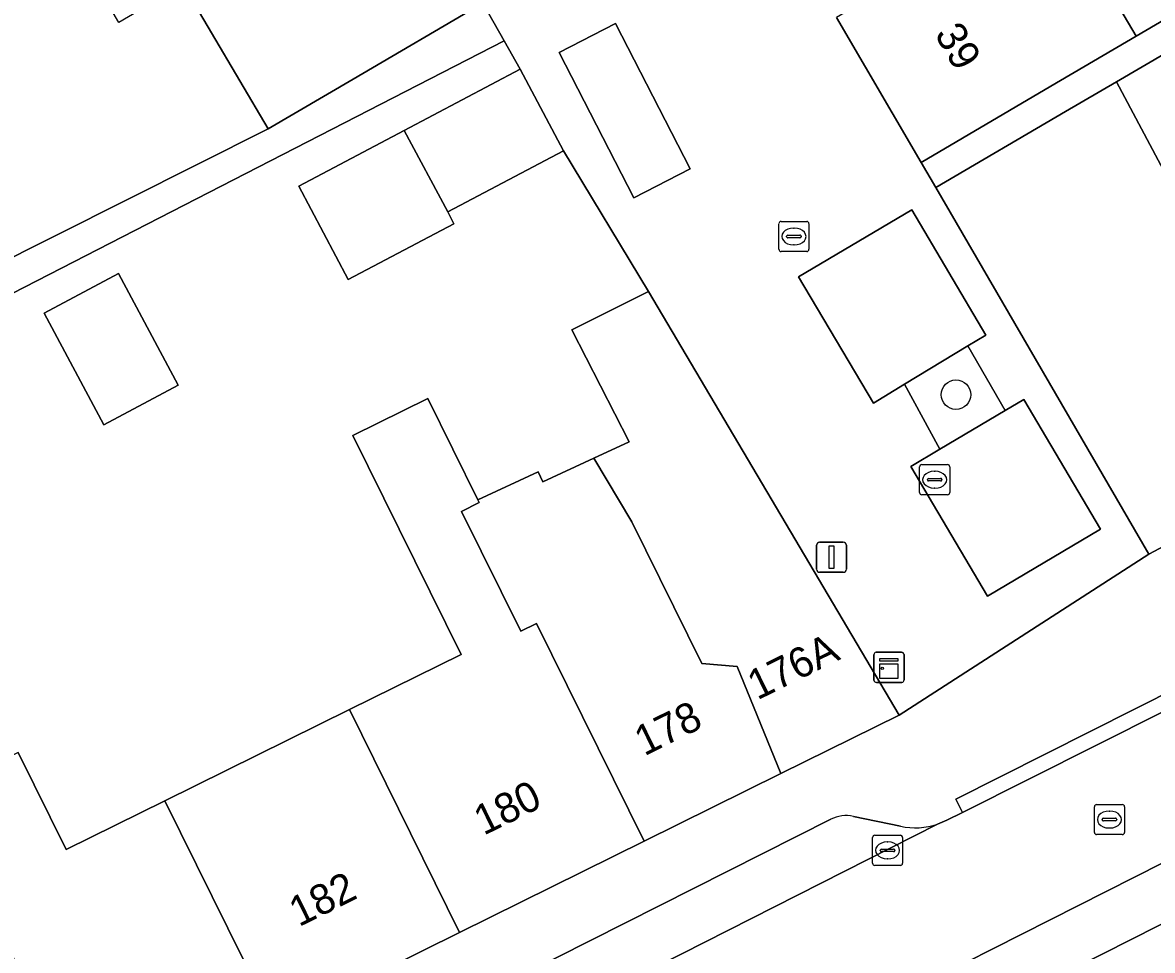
# Model space of a CAD drawing. Extents: x 161771 to 163125, y 382475 to 383179.
# Drawn here: x 162276.97 to 162314.5, y 382695.7 to 382726.52 of the extents above; entities that cross this region are included whole.
import ezdxf

# ---------------------------------------------------------------- set-up
doc = ezdxf.new("R2010")
doc.units = 0
for name, color, linetype in [('IMGEO_Boom', 7, 'Continuous'), ('IMGEO_Erf', 7, 'Continuous'), ('IMGEO_Groenvoorziening', 7, 'Continuous'), ('IMGEO_Kast', 7, 'Continuous'), ('IMGEO_Kolk', 7, 'Continuous'), ('IMGEO_Lichtmast', 7, 'Continuous'), ('IMGEO_Muur', 7, 'Continuous'), ('IMGEO_Pand', 7, 'Continuous'), ('IMGEO_Pand_nummerreeks', 7, 'Continuous'), ('IMGEO_Parkeervlak_open', 7, 'Continuous'), ('IMGEO_Rijbaan_lokaal_open', 7, 'Continuous'), ('IMGEO_Rioolput', 7, 'Continuous'), ('IMGEO_Voetpad_open', 7, 'Continuous'), ('IMGEO_Woonerf_open', 7, 'Continuous')]:
    doc.layers.add(name, color=color, linetype=linetype)

msp = doc.modelspace()

# ---------------------------------------------------------------- linework, layer by layer
at = {"layer": 'IMGEO_Boom'}
msp.add_circle((162307.974, 382714.16), 0.489, dxfattribs=at)
at = {"layer": 'IMGEO_Erf'}
for points in [[(162275.724, 382718.276), (162285.12, 382722.995), (162282.305, 382727.783), (162280.165, 382726.529), (162277.514, 382731.054), (162274.864, 382735.578), (162276.989, 382736.823), (162274.331, 382741.344)], [(162320.333, 382736.234), (162311.14, 382730.859), (162313.959, 382726.072), (162319.628, 382729.406)], [(162276.82, 382702.277), (162278.412, 382699.054), (162281.691, 382700.673), (162287.824, 382703.703), (162291.531, 382705.534), (162287.94, 382712.804), (162290.429, 382714.032), (162292.093, 382710.663), (162294.095, 382711.595), (162294.25, 382711.263), (162295.939, 382712.049), (162297.114, 382712.596), (162295.216, 382716.318), (162297.757, 382717.589), (162294.932, 382722.26), (162291.09, 382720.229), (162291.297, 382719.84), (162287.785, 382717.983), (162286.143, 382721.089), (162289.645, 382722.94), (162293.496, 382724.976), (162292.966, 382725.916), (162274.561, 382716.472)]]:
    msp.add_lwpolyline(points, dxfattribs=at)
msp.add_lwpolyline([(162277.677, 382716.867), (162280.154, 382718.19), (162282.137, 382714.479), (162279.661, 382713.156)], close=True, dxfattribs=at)
at = {"layer": 'IMGEO_Groenvoorziening'}
msp.add_lwpolyline([(162307.44, 382712.352), (162309.608, 382713.635), (162308.371, 382715.782), (162306.267, 382714.505)], close=True, dxfattribs=at)
at = {"layer": 'IMGEO_Kast'}
for p, q in [((162305.248, 382704.676), (162305.248, 382705.517)), ((162305.248, 382705.517), (162305.248, 382704.676)), ((162305.323, 382705.601), (162306.164, 382705.601)), ((162306.164, 382705.601), (162305.323, 382705.601)), ((162306.248, 382705.526), (162306.248, 382704.685)), ((162306.248, 382704.685), (162306.248, 382705.526)), ((162306.173, 382704.601), (162305.332, 382704.601)), ((162305.332, 382704.601), (162306.173, 382704.601))]:
    msp.add_line(p, q, dxfattribs=at)
for points in [[(162305.443, 382705.391), (162306.043, 382705.391), (162306.043, 382705.306), (162305.443, 382705.306), (162305.443, 382705.391)], [(162305.443, 382705.216), (162306.043, 382705.216), (162306.043, 382704.727), (162305.443, 382704.727), (162305.443, 382705.216)]]:
    msp.add_lwpolyline(points, dxfattribs=at)
msp.add_circle((162305.527, 382705.065), 0.0377, dxfattribs=at)
for centre, start, end in [((162305.326, 382705.523), 92.4484, 184.2845), ((162305.326, 382705.523), 92.4484, 184.2845), ((162306.17, 382705.523), 2.4484, 94.2845), ((162306.17, 382705.523), 2.4484, 94.2845), ((162305.326, 382704.679), 182.4484, 274.2845), ((162305.326, 382704.679), 182.4484, 274.2845), ((162306.17, 382704.679), 272.4484, 4.2845), ((162306.17, 382704.679), 272.4484, 4.2845)]:
    msp.add_arc(centre, 0.0779, start, end, dxfattribs=at)
at = {"layer": 'IMGEO_Kolk'}
for p, q in [((162302.09, 382718.989), (162302.09, 382719.841)), ((162302.165, 382719.915), (162303.017, 382719.915)), ((162302.578, 382719.695), (162302.603, 382719.695)), ((162303.091, 382719.841), (162303.091, 382718.989)), ((162302.349, 382719.409), (162302.349, 382719.421)), ((162302.787, 382719.372), (162302.389, 382719.372)), ((162302.392, 382719.458), (162302.79, 382719.458)), ((162302.833, 382719.421), (162302.833, 382719.409)), ((162303.017, 382718.915), (162302.165, 382718.915)), ((162302.601, 382719.135), (162302.576, 382719.135)), ((162306.766, 382710.91), (162306.766, 382711.762)), ((162306.841, 382711.836), (162307.693, 382711.836)), ((162307.767, 382711.762), (162307.767, 382710.91)), ((162307.025, 382711.33), (162307.025, 382711.342)), ((162307.068, 382711.379), (162307.466, 382711.379)), ((162307.254, 382711.616), (162307.279, 382711.616)), ((162307.509, 382711.342), (162307.509, 382711.33)), ((162307.463, 382711.293), (162307.065, 382711.293)), ((162307.277, 382711.056), (162307.252, 382711.056)), ((162307.693, 382710.836), (162306.841, 382710.836)), ((162305.201, 382698.596), (162305.201, 382699.448)), ((162305.276, 382699.522), (162306.128, 382699.522)), ((162306.202, 382699.448), (162306.202, 382698.596)), ((162305.46, 382699.016), (162305.46, 382699.028)), ((162305.898, 382698.979), (162305.5, 382698.979)), ((162305.503, 382699.065), (162305.901, 382699.065)), ((162305.689, 382699.302), (162305.714, 382699.302)), ((162305.944, 382699.028), (162305.944, 382699.016)), ((162305.712, 382698.742), (162305.687, 382698.742)), ((162306.128, 382698.522), (162305.276, 382698.522))]:
    msp.add_line(p, q, dxfattribs=at)
for points in [[(162302.09, 382718.989), (162302.09, 382719.841)], [(162302.165, 382719.915), (162303.017, 382719.915)], [(162303.091, 382719.841), (162303.091, 382718.989)], [(162303.017, 382718.915), (162302.165, 382718.915)], [(162306.766, 382710.91), (162306.766, 382711.762)], [(162306.841, 382711.836), (162307.693, 382711.836)], [(162307.767, 382711.762), (162307.767, 382710.91)], [(162307.693, 382710.836), (162306.841, 382710.836)], [(162305.201, 382698.596), (162305.201, 382699.448)], [(162305.276, 382699.522), (162306.128, 382699.522)], [(162306.202, 382699.448), (162306.202, 382698.596)], [(162306.128, 382698.522), (162305.276, 382698.522)]]:
    msp.add_lwpolyline(points, dxfattribs=at)
for centre, radius, start, end in [((162302.167, 382719.839), 0.0765, 91.552, 178.448), ((162302.167, 382719.839), 0.0765, 91.552, 178.448), ((162303.015, 382719.839), 0.0765, 1.552, 88.448), ((162303.015, 382719.839), 0.0765, 1.552, 88.448), ((162302.389, 382719.418), 0.0403, 85.8775, 175.7526), ((162302.386, 382719.408), 0.0366, 178.938, 274.7102), ((162302.79, 382719.415), 0.043, 264.8664, 352.4533), ((162302.794, 382719.42), 0.0386, 1.7309, 96.639), ((162302.167, 382718.991), 0.0765, 181.552, 268.448), ((162302.167, 382718.991), 0.0765, 181.552, 268.448), ((162303.015, 382718.991), 0.0765, 271.552, 358.448), ((162303.015, 382718.991), 0.0765, 271.552, 358.448), ((162306.843, 382711.76), 0.0765, 91.552, 178.448), ((162306.843, 382711.76), 0.0765, 91.552, 178.448), ((162307.691, 382711.76), 0.0765, 1.552, 88.448), ((162307.691, 382711.76), 0.0765, 1.552, 88.448), ((162307.065, 382711.339), 0.0403, 85.8775, 175.7526), ((162307.47, 382711.341), 0.0386, 1.7309, 96.639), ((162307.062, 382711.329), 0.0366, 178.938, 274.7102), ((162307.466, 382711.336), 0.043, 264.8664, 352.4533), ((162306.843, 382710.912), 0.0765, 181.552, 268.448), ((162306.843, 382710.912), 0.0765, 181.552, 268.448), ((162307.691, 382710.912), 0.0765, 271.552, 358.448), ((162307.691, 382710.912), 0.0765, 271.552, 358.448), ((162305.278, 382699.446), 0.0765, 91.552, 178.448), ((162305.278, 382699.446), 0.0765, 91.552, 178.448), ((162306.126, 382699.446), 0.0765, 1.552, 88.448), ((162306.126, 382699.446), 0.0765, 1.552, 88.448), ((162305.5, 382699.025), 0.0403, 85.8775, 175.7526), ((162305.497, 382699.015), 0.0366, 178.938, 274.7102), ((162305.901, 382699.022), 0.043, 264.8664, 352.4533), ((162305.905, 382699.027), 0.0386, 1.7309, 96.639), ((162305.278, 382698.598), 0.0765, 181.552, 268.448), ((162305.278, 382698.598), 0.0765, 181.552, 268.448), ((162306.126, 382698.598), 0.0765, 271.552, 358.448), ((162306.126, 382698.598), 0.0765, 271.552, 358.448)]:
    msp.add_arc(centre, radius, start, end, dxfattribs=at)
for centre, major_axis, ratio, start_param, end_param in [((162302.577, 382719.415), (-0.387, 0.002), 0.722429, 4.712389, 7.853982), ((162302.602, 382719.415), (-0.39, 0.002), 0.717154, 1.570796, 4.712389), ((162307.253, 382711.336), (-0.387, 0.002), 0.722429, 4.712389, 7.853982), ((162307.278, 382711.336), (-0.39, 0.002), 0.717154, 1.570796, 4.712389), ((162305.688, 382699.022), (-0.387, 0.002), 0.722429, 4.712389, 7.853982), ((162305.713, 382699.022), (-0.39, 0.002), 0.717154, 1.570796, 4.712389)]:
    msp.add_ellipse(centre, major_axis=major_axis, ratio=ratio, start_param=start_param, end_param=end_param, dxfattribs=at)
at = {"layer": 'IMGEO_Lichtmast'}
for p, q in [((162303.342, 382708.36), (162303.342, 382709.16)), ((162303.342, 382709.16), (162303.342, 382708.36)), ((162303.442, 382709.26), (162304.232, 382709.26)), ((162304.232, 382709.26), (162303.442, 382709.26)), ((162304.332, 382709.16), (162304.332, 382708.36)), ((162304.332, 382708.36), (162304.332, 382709.16)), ((162304.232, 382708.26), (162303.442, 382708.26)), ((162303.442, 382708.26), (162304.232, 382708.26))]:
    msp.add_line(p, q, dxfattribs=at)
msp.add_lwpolyline([(162303.762, 382709.135), (162303.912, 382709.135), (162303.912, 382708.385), (162303.762, 382708.385), (162303.762, 382709.135)], dxfattribs=at)
for centre, start, end in [((162303.442, 382709.16), 90, 180), ((162303.442, 382709.16), 90, 180), ((162304.232, 382709.16), 0, 90), ((162304.232, 382709.16), 360, 90), ((162303.442, 382708.36), 180, 270), ((162303.442, 382708.36), 180, 270), ((162304.232, 382708.36), 270, 0), ((162304.232, 382708.36), 270, 0)]:
    msp.add_arc(centre, 0.1, start, end, dxfattribs=at)
at = {"layer": 'IMGEO_Muur'}
msp.add_lwpolyline([(162297.757, 382717.589), (162294.932, 382722.26)], dxfattribs=at)
at = {"layer": 'IMGEO_Pand'}
for points in [[(162282.305, 382727.783), (162285.12, 382722.995), (162287.943, 382724.646), (162292.259, 382727.17), (162289.442, 382731.963)], [(162311.14, 382730.859), (162310.946, 382730.745), (162304.003, 382726.686), (162306.82, 382721.874), (162311.131, 382724.409), (162313.959, 382726.072)], [(162321.429, 382722.643), (162318.523, 382721.051), (162318.3, 382721.471), (162315.862, 382726.049), (162313.303, 382724.551), (162320.055, 382711.869), (162325.601, 382714.806)], [(162289.645, 382722.94), (162291.09, 382720.229), (162294.932, 382722.26), (162293.496, 382724.976)], [(162313.303, 382724.551), (162311.616, 382723.563), (162307.301, 382721.037), (162314.379, 382708.865), (162320.055, 382711.869)], [(162289.645, 382722.94), (162286.143, 382721.089), (162287.785, 382717.983), (162291.297, 382719.84), (162291.09, 382720.229)], [(162277.677, 382716.867), (162279.661, 382713.156), (162282.137, 382714.479), (162280.154, 382718.19)], [(162295.939, 382712.049), (162297.206, 382709.941), (162299.535, 382705.226), (162300.705, 382705.133), (162302.155, 382701.574), (162306.086, 382703.518), (162297.757, 382717.589), (162295.216, 382716.318), (162297.114, 382712.596)], [(162297.616, 382699.329), (162294.043, 382706.564), (162293.514, 382706.303), (162291.549, 382710.283), (162292.137, 382710.573), (162292.093, 382710.663), (162290.429, 382714.032), (162287.94, 382712.804), (162291.531, 382705.534), (162287.824, 382703.703), (162291.483, 382696.295)], [(162297.616, 382699.329), (162302.155, 382701.574), (162300.705, 382705.133), (162299.535, 382705.226), (162297.206, 382709.941), (162295.939, 382712.049), (162294.25, 382711.263), (162294.095, 382711.595), (162292.093, 382710.663), (162292.137, 382710.573), (162291.549, 382710.283), (162293.514, 382706.303), (162294.043, 382706.564)], [(162291.483, 382696.295), (162287.824, 382703.703), (162281.691, 382700.673), (162285.351, 382693.263)], [(162275.569, 382697.65), (162279.231, 382690.236), (162285.351, 382693.263), (162281.691, 382700.673), (162278.412, 382699.054), (162276.82, 382702.277), (162273.977, 382700.873)]]:
    msp.add_lwpolyline(points, close=True, dxfattribs=at)
at = {"layer": 'IMGEO_Parkeervlak_open'}
for points in [[(162401.256, 382747.01), (162400.386, 382746.491), (162370.2, 382728.476), (162367.741, 382727.079), (162354.685, 382720.034), (162351.77, 382718.461), (162349.822, 382717.41), (162348.194, 382716.555), (162332.897, 382708.52), (162326.104, 382704.354), (162325.132, 382703.807), (162292.384, 382687.247), (162288.66, 382685.364), (162272.146, 382677.013), (162226.284, 382653.729), (162225.203, 382653.3)], [(162226.19, 382651.795), (162226.475, 382651.909), (162227.961, 382652.66), (162244.337, 382660.938), (162247.835, 382662.706), (162249.289, 382663.441), (162252.798, 382665.214), (162272.969, 382675.41), (162322.131, 382700.285)], [(162306.134, 382699.822), (162304.567, 382700.152)], [(162270.89, 382681.387), (162286.63, 382689.373), (162290.352, 382691.261), (162307.363, 382699.892)], [(162303.813, 382700.054), (162273.029, 382684.522)]]:
    msp.add_lwpolyline(points, dxfattribs=at)
for points in [[(162297.27, 382720.701), (162299.148, 382721.668), (162296.664, 382726.49), (162294.787, 382725.523)], [(162306.503, 382720.304), (162302.742, 382718.078), (162305.229, 382713.875), (162306.267, 382714.505), (162308.371, 382715.782), (162308.969, 382716.136)], [(162309.608, 382713.635), (162307.44, 382712.352), (162306.47, 382711.778), (162309.02, 382707.47), (162312.781, 382709.695), (162310.231, 382714.004)]]:
    msp.add_lwpolyline(points, close=True, dxfattribs=at)
for centre, radius, start, end in [((162304.33, 382699.024), 1.153, 78.1479, 116.6629), ((162306.621, 382702.091), 2.32, 257.8776, 288.6422)]:
    msp.add_arc(centre, radius, start, end, dxfattribs=at)
at = {"layer": 'IMGEO_Rijbaan_lokaal_open'}
msp.add_lwpolyline([(162292.384, 382687.247), (162325.132, 382703.807), (162326.104, 382704.354), (162332.897, 382708.52), (162348.194, 382716.555), (162345.958, 382720.5), (162329.123, 382711.57), (162319.371, 382705.921), (162317.56, 382705.014), (162317.118, 382704.77), (162308.192, 382700.282), (162307.672, 382700.021), (162307.363, 382699.892), (162290.352, 382691.261)], close=True, dxfattribs=at)
at = {"layer": 'IMGEO_Rioolput'}
for p, q in [((162312.573, 382699.619), (162312.573, 382700.471)), ((162312.648, 382700.545), (162313.5, 382700.545)), ((162313.574, 382700.471), (162313.574, 382699.619)), ((162312.875, 382700.088), (162313.273, 382700.088)), ((162313.061, 382700.325), (162313.086, 382700.325)), ((162312.832, 382700.039), (162312.832, 382700.051)), ((162313.27, 382700.002), (162312.872, 382700.002)), ((162313.084, 382699.765), (162313.059, 382699.765)), ((162313.316, 382700.051), (162313.316, 382700.039)), ((162313.5, 382699.545), (162312.648, 382699.545))]:
    msp.add_line(p, q, dxfattribs=at)
for points in [[(162312.573, 382699.619), (162312.573, 382700.471)], [(162312.648, 382700.545), (162313.5, 382700.545)], [(162313.574, 382700.471), (162313.574, 382699.619)], [(162313.5, 382699.545), (162312.648, 382699.545)]]:
    msp.add_lwpolyline(points, dxfattribs=at)
for centre, radius, start, end in [((162312.65, 382700.469), 0.0765, 91.552, 178.448), ((162312.65, 382700.469), 0.0765, 91.552, 178.448), ((162313.498, 382700.469), 0.0765, 1.552, 88.448), ((162313.498, 382700.469), 0.0765, 1.552, 88.448), ((162312.872, 382700.048), 0.0403, 85.8775, 175.7526), ((162313.277, 382700.05), 0.0386, 1.7309, 96.639), ((162312.869, 382700.038), 0.0366, 178.938, 274.7102), ((162313.273, 382700.045), 0.043, 264.8664, 352.4533), ((162312.65, 382699.621), 0.0765, 181.552, 268.448), ((162312.65, 382699.621), 0.0765, 181.552, 268.448), ((162313.498, 382699.621), 0.0765, 271.552, 358.448), ((162313.498, 382699.621), 0.0765, 271.552, 358.448)]:
    msp.add_arc(centre, radius, start, end, dxfattribs=at)
for centre, major_axis, ratio, start_param, end_param in [((162313.06, 382700.045), (-0.387, 0.002), 0.722429, 4.712389, 7.853982), ((162313.085, 382700.045), (-0.39, 0.002), 0.717154, 1.570796, 4.712389)]:
    msp.add_ellipse(centre, major_axis=major_axis, ratio=ratio, start_param=start_param, end_param=end_param, dxfattribs=at)
at = {"layer": 'IMGEO_Voetpad_open'}
for points in [[(162289.568, 382788.823), (162306.253, 382760.786), (162323.401, 382731.624), (162323.014, 382731.397), (162319.628, 382729.406), (162313.959, 382726.072), (162311.131, 382724.409), (162306.82, 382721.874), (162307.301, 382721.037), (162311.616, 382723.563), (162313.303, 382724.551), (162315.862, 382726.049), (162335.582, 382737.558), (162337.492, 382738.692), (162341.806, 382741.253), (162341.308, 382742.121), (162336.992, 382739.597), (162334.281, 382738.012), (162324.79, 382732.441), (162302.938, 382768.724), (162300.444, 382772.865), (162279.118, 382808.764)], [(162236.7, 382780.702), (162237.919, 382778.787), (162238.079, 382778.879), (162251.659, 382755.156), (162256.533, 382746.747), (162256.965, 382746.022), (162274.561, 382716.472), (162292.966, 382725.916), (162292.259, 382727.17), (162287.943, 382724.646), (162285.12, 382722.995), (162275.724, 382718.276), (162274.221, 382718.839), (162261.653, 382739.71), (162252.527, 382755.653), (162241.901, 382774.216), (162241.795, 382774.154), (162240.563, 382776.247), (162240.694, 382776.324), (162238.013, 382781.007)], [(162367.842, 382737.655), (162362.258, 382734.314), (162358.717, 382732.229), (162358.035, 382731.885), (162358.174, 382731.65), (162355.992, 382730.412), (162355.795, 382730.757), (162354.077, 382729.857), (162349.794, 382727.612), (162343.623, 382724.345), (162342.999, 382724.015), (162337.534, 382721.122), (162337.243, 382720.968), (162331.462, 382717.908), (162325.601, 382714.806), (162320.055, 382711.869), (162314.379, 382708.865), (162306.086, 382703.518), (162302.155, 382701.574), (162297.616, 382699.329), (162291.483, 382696.295), (162285.351, 382693.263), (162279.231, 382690.236), (162272.685, 382687.085)], [(162364.537, 382723.338), (162355.646, 382718.545), (162351.203, 382716.149), (162340.36, 382710.431), (162340.558, 382710.011), (162337.871, 382708.613), (162337.639, 382708.996), (162333.213, 382706.662), (162326.62, 382702.597), (162326.85, 382702.154), (162322.758, 382700.031), (162322.528, 382700.474), (162322.131, 382700.285), (162272.969, 382675.41)], [(162307.363, 382699.892), (162307.672, 382700.021), (162308.192, 382700.282), (162307.968, 382700.728), (162316.894, 382705.216), (162317.118, 382704.77), (162317.56, 382705.014)], [(162304.567, 382700.152), (162306.134, 382699.822)], [(162273.029, 382684.522), (162303.813, 382700.054)]]:
    msp.add_lwpolyline(points, dxfattribs=at)
msp.add_lwpolyline([(162317.118, 382704.77), (162316.894, 382705.216), (162307.968, 382700.728), (162308.192, 382700.282)], close=True, dxfattribs=at)
for centre, radius, start, end in [((162304.33, 382699.024), 1.153, 78.1479, 116.6629), ((162306.621, 382702.091), 2.32, 257.8776, 288.6422)]:
    msp.add_arc(centre, radius, start, end, dxfattribs=at)
at = {"layer": 'IMGEO_Woonerf_open'}
msp.add_lwpolyline([(162292.259, 382727.17), (162292.966, 382725.916), (162293.496, 382724.976), (162294.932, 382722.26), (162297.757, 382717.589), (162306.086, 382703.518), (162314.379, 382708.865), (162307.301, 382721.037), (162306.82, 382721.874), (162304.003, 382726.686)], dxfattribs=at)
for points in [[(162296.664, 382726.49), (162299.148, 382721.668), (162297.27, 382720.701), (162294.787, 382725.523)], [(162306.503, 382720.304), (162308.969, 382716.136), (162308.371, 382715.782), (162309.608, 382713.635), (162310.231, 382714.004), (162312.781, 382709.695), (162309.02, 382707.47), (162306.47, 382711.778), (162307.44, 382712.352), (162306.267, 382714.505), (162305.229, 382713.875), (162302.742, 382718.078)]]:
    msp.add_lwpolyline(points, close=True, dxfattribs=at)

# ---------------------------------------------------------------- texts
at = {"layer": 'IMGEO_Pand_nummerreeks'}
for s, rotation, p in [('39', 300.3472, (162307.245, 382726.137)), ('176A', 26.3166, (162301.374, 382703.999)), ('178', 26.3166, (162297.618, 382702.142)), ('180', 26.3166, (162292.282, 382699.503)), ('182', 26.3166, (162286.144, 382696.467))]:
    msp.add_text(s, height=1, rotation=rotation, dxfattribs=at).set_placement(p)

doc.saveas('drawing.dxf')
